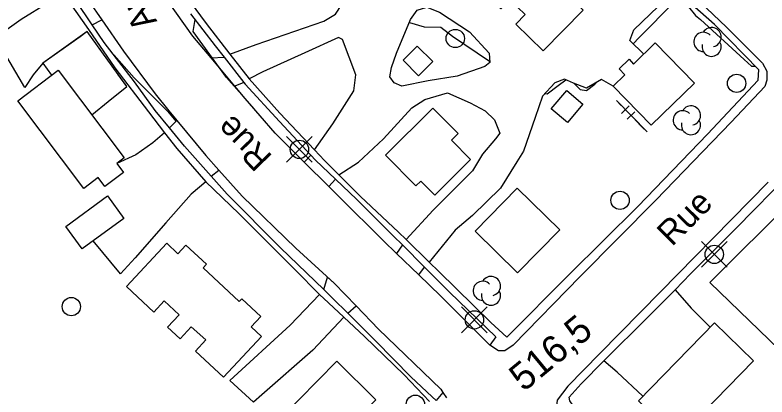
# Model space of a CAD drawing. Extents: x 347059 to 352153, y 6073752 to 6078601.
# Drawn here: x 348460.7 to 348583.7, y 6074685.5 to 6074748 of the extents above; entities that cross this region are included whole.
import ezdxf

# ---------------------------------------------------------------- set-up
doc = ezdxf.new("R2010")
doc.units = 0
for name, color, linetype in [('Level 19', 7, 'Continuous'), ('Level 2', 7, 'Continuous'), ('Level 21', 7, 'Continuous'), ('Level 22', 7, 'Continuous'), ('Level 3', 7, 'Continuous'), ('Level 31', 7, 'Continuous'), ('Level 36', 7, 'Continuous'), ('Level 37', 7, 'Continuous'), ('Level 44', 7, 'Continuous')]:
    doc.layers.add(name, color=color, linetype=linetype)

msp = doc.modelspace()

# ---------------------------------------------------------------- linework, layer by layer
at = {"layer": 'Level 19'}
for points in [[(348495.85, 6074741.6), (348500.13, 6074743.22), (348511.2, 6074747.03), (348513.11, 6074748.17), (348516.48, 6074753.3), (348519.19, 6074760.12), (348522.16, 6074763.94), (348524.2, 6074766.99), (348525.58, 6074769.68)], [(348563.56, 6074741.62), (348561.31, 6074743.87), (348561.96, 6074745.61), (348567.31, 6074750.8), (348568.74, 6074752.16)], [(348465.27, 6074740.17), (348463.66, 6074738.23), (348462.28, 6074736.19), (348457.44, 6074744.34), (348461.72, 6074747.36), (348466.11, 6074750.11), (348468.57, 6074751.63)], [(348523.11, 6074741.8), (348525.42, 6074747.31), (348526.5, 6074748.81), (348528.1, 6074749.32), (348530.15, 6074748.48), (348535.06, 6074745.29), (348538.26, 6074741.81), (348538.37, 6074740.25), (348537.57, 6074739.59), (348533.04, 6074738), (348528.31, 6074737.28), (348524.01, 6074736.4), (348522.75, 6074736.93), (348522.02, 6074737.89), (348522.29, 6074739.46), (348523.11, 6074741.8)], [(348473.3, 6074746.45), (348474.91, 6074747.24)], [(348509.67, 6074725.97), (348512.72, 6074730.23), (348516.12, 6074735.6), (348516.48, 6074738.23), (348514.27, 6074744.02), (348513.64, 6074744.33), (348508.13, 6074741.84), (348501.22, 6074738.71), (348498.98, 6074737.56)], [(348492.77, 6074741), (348494.9, 6074741.12)], [(348558.56, 6074736.38), (348556.66, 6074737.49), (348554.19, 6074736.04), (348552.06, 6074736.89), (348550.6, 6074737.55), (348549.03, 6074736.92), (348546.98, 6074734.74), (348545.82, 6074731.24), (348543.91, 6074725.75), (348542.82, 6074724.01), (348540.15, 6074719.71), (348535.53, 6074715.21), (348532.73, 6074712.79), (348528.46, 6074707.6)], [(348498.13, 6074737), (348496.67, 6074736.38)], [(348513.67, 6074721.87), (348516.89, 6074723.94), (348520.96, 6074727.78), (348525.6, 6074732.84), (348527.77, 6074734.19), (348531.43, 6074735.29), (348535.17, 6074733.68), (348537.63, 6074732.36), (348539.17, 6074730.87), (348540, 6074728.71), (348539.3, 6074727.75), (348537.2, 6074725.28), (348535.52, 6074722.5), (348529.09, 6074716.11), (348524.69, 6074711.26)], [(348485.95, 6074729.55), (348487.19, 6074730.74)], [(348485.17, 6074728.76), (348483.22, 6074727.13), (348480.46, 6074725.14), (348477.34, 6074723.75)], [(348508, 6074723.97), (348509.12, 6074725.07)], [(348492.77, 6074721.67), (348494.04, 6074722.65)], [(348491.92, 6074720.74), (348489.49, 6074718.7), (348485.38, 6074714.01), (348480.36, 6074708.26), (348477.95, 6074705.64), (348473.5, 6074711.06)], [(348512.02, 6074719.98), (348513.14, 6074721.18)], [(348524.08, 6074710.39), (348523.09, 6074709)], [(348526.75, 6074705.48), (348527.72, 6074706.73)], [(348511.2, 6074703.1), (348511.83, 6074705.14)], [(348568.7, 6074703.06), (348571.35, 6074700.04), (348574.43, 6074696.92)], [(348514.49, 6074698.57), (348509.41, 6074693.15), (348501.09, 6074685.86), (348499.71, 6074684.63), (348495.85, 6074688.22), (348505.71, 6074697.25), (348510.51, 6074702.29)], [(348515.15, 6074699.22), (348516.52, 6074700.4)], [(348563.44, 6074685.65), (348559.22, 6074689.56), (348557.03, 6074691.41)]]:
    msp.add_lwpolyline(points, dxfattribs=at)
at = {"layer": 'Level 2'}
for points in [[(348561.85, 6074743.33), (348562.83, 6074744.36), (348568.59, 6074750.21), (348569.6, 6074750.27), (348570.89, 6074749.37), (348572.04, 6074747.97), (348572.85, 6074747.3), (348580.02, 6074740.75), (348581.22, 6074739.64), (348581.72, 6074739.64), (348581.77, 6074739.68)], [(348499.87, 6074732.61), (348499.9, 6074732.64), (348495.29, 6074737.8), (348489.84, 6074745.33), (348490.15, 6074747.29)], [(348525.22, 6074746.83), (348527.66, 6074746.12), (348530.37, 6074746.03), (348532.26, 6074744.58), (348538.35, 6074740.49)], [(348476.9, 6074741.44), (348480.18, 6074737.74), (348485.62, 6074732.3), (348487.06, 6074730.62)], [(348547.39, 6074735.17), (348547.78, 6074735.12), (348549.54, 6074736.49), (348550.82, 6074737.45)], [(348552.17, 6074736.84), (348553.14, 6074735.82), (348554.2, 6074735.66), (348555.57, 6074736.7), (348555.89, 6074737.04)]]:
    msp.add_lwpolyline(points, dxfattribs=at)
at = {"layer": 'Level 21'}
for points in [[(348446.38, 6074803.45), (348449.02, 6074795.85), (348449.94, 6074793.62), (348452.44, 6074787.6), (348454.7, 6074782.32), (348455.82, 6074779.69), (348457.68, 6074775.9), (348459.99, 6074771.18), (348464.5, 6074763.61), (348467.72, 6074757.59), (348470.62, 6074753.42), (348474.91, 6074747.24), (348478.47, 6074742.11), (348483.6, 6074735.14), (348485.85, 6074732.36), (348487.19, 6074730.74), (348491.89, 6074725.03), (348494.04, 6074722.65), (348497.88, 6074718.4), (348506.63, 6074709.88), (348512.93, 6074704.14)], [(348569.41, 6074753.39), (348577.08, 6074746.03), (348582.98, 6074740.17), (348583.69, 6074738.86), (348583.72, 6074737.37), (348583.39, 6074736.32), (348577.87, 6074730.47), (348565.56, 6074717.75), (348553.18, 6074705.21), (348542.19, 6074693.99), (348540.83, 6074693.08), (348539.8, 6074693.05), (348538.41, 6074694.01), (348530.31, 6074702.05), (348526.75, 6074705.48), (348523.09, 6074709), (348520.97, 6074711.05), (348513.73, 6074718.28), (348512.02, 6074719.98), (348508, 6074723.97), (348503.26, 6074728.67), (348498.34, 6074734.39), (348496.67, 6074736.38), (348492.77, 6074741), (348489.77, 6074744.57), (348484.16, 6074752.56)], [(348583.93, 6074720.65), (348571.99, 6074708.48), (348566.32, 6074702.72), (348556.37, 6074692.61), (348551.14, 6074687.28)], [(348511.83, 6074705.14), (348512.93, 6074704.14), (348516.52, 6074700.4), (348520.14, 6074696.63), (348530.35, 6074686.78), (348530.71, 6074686.24), (348531.29, 6074685.37)], [(348551.14, 6074687.28), (348549.38, 6074684.96), (348549.3, 6074683.97), (348549.83, 6074682.97), (348550.14, 6074682.56), (348551.75, 6074680.48), (348561.83, 6074670.76), (348572.38, 6074659.86), (348585.9, 6074647.36), (348597.48, 6074635.74), (348608.59, 6074624.43), (348611.5, 6074621.72), (348620.94, 6074612.88), (348628.61, 6074605.45), (348632.8, 6074601.29), (348638.41, 6074595.71), (348644.63, 6074589.63), (348650.66, 6074583.73), (348659.54, 6074575.29), (348666.46, 6074568.38), (348672.58, 6074562.54), (348683.78, 6074551.29)]]:
    msp.add_lwpolyline(points, dxfattribs=at)
at = {"layer": 'Level 22'}
for points in [[(348530.71, 6074686.24), (348529.6, 6074684.95), (348528.97, 6074685.51), (348525.47, 6074688.82), (348519.73, 6074694.65), (348515.15, 6074699.22), (348512.72, 6074701.64), (348511.2, 6074703.1), (348504.11, 6074709.9), (348495.42, 6074718.7), (348492.77, 6074721.67), (348488.4, 6074726.56), (348485.95, 6074729.55), (348483.62, 6074732.39), (348480.24, 6074737.07), (348475.3, 6074743.53), (348473.3, 6074746.45), (348472.2, 6074748.06), (348469.46, 6074752.16), (348466.47, 6074756.63), (348461.63, 6074765.04), (348457.69, 6074772.55)], [(348457.8, 6074769.37), (348462.13, 6074762.11), (348464.67, 6074757.63), (348468.33, 6074751.98), (348468.57, 6074751.63), (348472.71, 6074745.66), (348477.05, 6074739.38), (348482.53, 6074732.18), (348485.17, 6074728.76), (348487.17, 6074726.16), (348491.92, 6074720.74), (348497.3, 6074715.56), (348506.52, 6074706.3), (348510.51, 6074702.29), (348512, 6074700.91)], [(348486.71, 6074753.8), (348491.95, 6074746.62), (348495.85, 6074741.6), (348498.98, 6074737.56), (348504.04, 6074731.96), (348509.67, 6074725.97), (348511.31, 6074724.23), (348513.67, 6074721.87), (348517.24, 6074718.3), (348523.45, 6074712.46), (348524.69, 6074711.26), (348528.46, 6074707.6), (348530.05, 6074706.05), (348538.54, 6074697.72), (348541.17, 6074695.28), (348551.37, 6074705.54), (348562.6, 6074716.66), (348574.02, 6074728.54), (348582.26, 6074737.38), (348582.37, 6074739.07), (348575.16, 6074746.5), (348568.74, 6074752.16)], [(348489.42, 6074748.24), (348493.44, 6074742.97), (348494.9, 6074741.12), (348498.13, 6074737), (348498.35, 6074736.72), (348503.98, 6074730.61), (348509.12, 6074725.07), (348509.86, 6074724.28), (348513.14, 6074721.18), (348516.64, 6074717.86), (348522.64, 6074711.84), (348524.08, 6074710.39), (348527.72, 6074706.73), (348531.76, 6074702.66), (348539.39, 6074695.37), (348538.41, 6074694.01)], [(348586.84, 6074650.39), (348580.19, 6074656.96), (348573.86, 6074662.97), (348568.45, 6074668.22), (348558.4, 6074677.8), (348551.97, 6074684.19), (348551.46, 6074684.9), (348551.38, 6074685.45), (348553.3, 6074687.67), (348557.03, 6074691.41), (348564.3, 6074698.6), (348568.7, 6074703.06), (348571.23, 6074705.64), (348578.7, 6074713.14), (348587.57, 6074722.2)], [(348512, 6074700.91), (348514.49, 6074698.57), (348517.86, 6074695.39), (348524.34, 6074689.12), (348528.49, 6074684.76)]]:
    msp.add_lwpolyline(points, dxfattribs=at)
at = {"layer": 'Level 31'}
for points in [[(348537.68, 6074754.63), (348535.95, 6074752.87), (348531.42, 6074757.3), (348537.96, 6074764), (348539.74, 6074762.26), (348541.17, 6074763.72), (348553.23, 6074751.94), (348551.88, 6074750.56), (348553.63, 6074748.84), (348547.1, 6074742.15), (348542.64, 6074746.51), (348544.19, 6074748.1), (348541.66, 6074750.58), (348540.18, 6074749.07), (348538.51, 6074750.7), (348540.07, 6074752.3), (348537.68, 6074754.63)], [(348559.54, 6074739.2), (348561.16, 6074740.78), (348561.91, 6074740.01), (348565.45, 6074743.46), (348571.87, 6074736.88), (348564.79, 6074729.98), (348558.56, 6074736.38), (348560.46, 6074738.23), (348559.54, 6074739.2)], [(348529.03, 6074740.42), (348526.69, 6074738.1), (348524.18, 6074740.64), (348526.51, 6074742.95), (348529.03, 6074740.42)], [(348471.94, 6074719.66), (348461.16, 6074734.01), (348467.77, 6074738.98), (348478.53, 6074724.65), (348477.34, 6074723.75), (348478.47, 6074722.25), (348475.41, 6074719.95), (348474.3, 6074721.43), (348471.94, 6074719.66)], [(348553.62, 6074733.43), (348551.07, 6074730.45), (348548.44, 6074732.7), (348550.99, 6074735.68), (348553.62, 6074733.43)], [(348526.3, 6074720.06), (348521.29, 6074725.07), (348529.03, 6074732.8), (348533.19, 6074728.62), (348532.09, 6074727.52), (348535.23, 6074724.37), (348529.39, 6074718.53), (348527.09, 6074720.84), (348526.3, 6074720.06)], [(348542.92, 6074705.82), (348535.96, 6074712.64), (348542.85, 6074719.68), (348549.82, 6074712.85), (348542.92, 6074705.82)], [(348469, 6074713.41), (348475.82, 6074718.41), (348478.52, 6074714.74), (348471.69, 6074709.74), (348469, 6074713.41)], [(348487.36, 6074708.95), (348488.67, 6074710.35), (348492, 6074707.23), (348491.46, 6074706.67), (348497.37, 6074701.14), (348497.8, 6074701.59), (348500.89, 6074698.69), (348499.31, 6074697.01), (348501.02, 6074695.41), (348494.79, 6074688.77), (348490.24, 6074693.03), (348491.94, 6074694.84), (348489.51, 6074696.99), (348487.69, 6074695.04), (348485.66, 6074696.94), (348487.54, 6074698.95), (348485.11, 6074701.23), (348483.39, 6074699.4), (348478.91, 6074703.59), (348485.53, 6074710.67), (348487.36, 6074708.95)], [(348562.68, 6074684.87), (348575.16, 6074697.67), (348581.55, 6074691.43), (348569.07, 6074678.63), (348562.68, 6074684.87)], [(348500.91, 6074678.71), (348513.33, 6074691.35), (348519.75, 6074685.04), (348507.33, 6074672.4), (348500.91, 6074678.71)]]:
    msp.add_lwpolyline(points, dxfattribs=at)
at = {"layer": 'Level 36'}
for p, q in [((348509.34, 6074723.92), (348505.11, 6074728.15)), ((348505.11, 6074723.92), (348509.34, 6074728.15)), ((348577.22, 6074706.73), (348572.99, 6074710.96)), ((348572.99, 6074706.73), (348577.22, 6074710.96)), ((348537.97, 6074696.01), (348533.74, 6074700.24)), ((348533.74, 6074696.01), (348537.97, 6074700.24))]:
    msp.add_line(p, q, dxfattribs=at)
for centre in [(348532.73, 6074744.19), (348578.76, 6074736.85), (348507.23, 6074726.04), (348559.69, 6074717.7), (348575.11, 6074708.85), (348469.91, 6074700.3), (348535.86, 6074698.13), (348526.2, 6074684.31)]:
    msp.add_circle(centre, 1.5, dxfattribs=at)
at = {"layer": 'Level 37'}
for p, q in [((348559.09, 6074734.02), (348559.86, 6074733.23)), ((348562.17, 6074730.88), (348563.33, 6074729.7)), ((348563.33, 6074729.7), (348564.1, 6074728.91))]:
    msp.add_line(p, q, dxfattribs=at)
for points in [[(348473.26, 6074731.68), (348475.96, 6074733.86), (348479.01, 6074736.32), (348472.52, 6074745.32), (348465.26, 6074740.17), (348466.69, 6074738.16)], [(348475.19, 6074741.62), (348472.52, 6074745.32), (348471.35, 6074744.48)], [(348471.35, 6074744.48), (348465.26, 6074740.17), (348466.69, 6074738.16)], [(348473.26, 6074731.68), (348475.96, 6074733.86), (348479.01, 6074736.32), (348477.53, 6074738.37)], [(348559.09, 6074734.02), (348564.1, 6074728.91)], [(348559.93, 6074731.91), (348561.18, 6074733.14)], [(348560.56, 6074732.53), (348561.48, 6074731.58)], [(348560.85, 6074730.97), (348562.11, 6074732.2)], [(348590.2, 6074715.6), (348587.99, 6074717.82), (348574.37, 6074704.25), (348587.28, 6074691.74), (348600.89, 6074705.39), (348597.09, 6074708.86)]]:
    msp.add_lwpolyline(points, dxfattribs=at)
at = {"layer": 'Level 44'}
for centre, start, end in [((348574.67, 6074744.41), 282.2692, 149.7263), ((348573.32, 6074743.63), 44.1154, 269.804), ((348574.67, 6074742.84), 166.9369, 29.6212), ((348569.94, 6074730.8), 44.1154, 269.804), ((348571.29, 6074731.58), 282.2692, 149.7263), ((348571.29, 6074730.01), 166.9369, 29.6212), ((348538.57, 6074703.67), 282.2692, 149.7263), ((348537.22, 6074702.89), 44.1154, 269.804), ((348538.57, 6074702.1), 166.9369, 29.6212)]:
    msp.add_arc(centre, 1.57, start, end, dxfattribs=at)

# ---------------------------------------------------------------- texts
at = {"layer": 'Level 21'}
for s, rotation, p in [('Aplow cr', 122.1025, (348484.01, 6074747.02)), ('Rue', 134.1007, (348502.96, 6074724.9)), ('Rue', 45.2171, (348568.19, 6074710.03))]:
    msp.add_text(s, height=4, rotation=rotation, dxfattribs=at).set_placement(p)
at = {"layer": 'Level 3'}
msp.add_text('516,5', height=4.5, rotation=39.62, dxfattribs=at).set_placement((348543.92, 6074686.24))

doc.saveas('drawing.dxf')
